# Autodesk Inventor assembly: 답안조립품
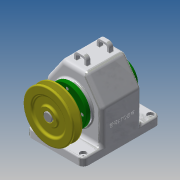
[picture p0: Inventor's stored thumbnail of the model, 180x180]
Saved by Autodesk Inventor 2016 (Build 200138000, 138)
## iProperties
Created: 2016-12
Part Number: 답안조립품
Document SubType Name: Assembly
Designer: Administrator
Author: Administrator
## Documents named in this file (15)
- D:\461207V1004\461207V1004\답안조립품.iam
- D:\461207V1004\461207V1004\본체.ipt
- D:\461207V1004\461207V1004\V-벨트풀리.ipt
- D:\461207V1004\461207V1004\뒤커버.ipt
- D:\461207V1004\461207V1004\멈춤나사 - M4x10.ipt
- D:\461207V1004\461207V1004\베어링 6203.ipt
- D:\461207V1004\461207V1004\볼트 M3 x 8.ipt
- D:\461207V1004\461207V1004\볼트 M3 x 10.ipt
- D:\461207V1004\461207V1004\부시.ipt
- D:\461207V1004\461207V1004\스퍼기어.ipt
- D:\461207V1004\461207V1004\앞커버.ipt
- D:\461207V1004\461207V1004\오일씰 28 40 8.ipt
- D:\461207V1004\461207V1004\축.ipt
- D:\461207V1004\461207V1004\키 - 5 x 5 x 18.ipt
- D:\461207V1004\461207V1004\키 - 6 x 6 x 22.ipt
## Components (9 placed, 3 different names)
1. V-벨트풀리:1
2. ISO 4762 M3 x 8:1
3. ISO 4762 M3 x 10:1
4. ISO 4762 M3 x 10:2
5. ISO 4762 M3 x 10:3
6. ISO 4762 M3 x 10:4
7. ISO 4762 M3 x 8:2
8. ISO 4762 M3 x 8:3
9. ISO 4762 M3 x 8:4
